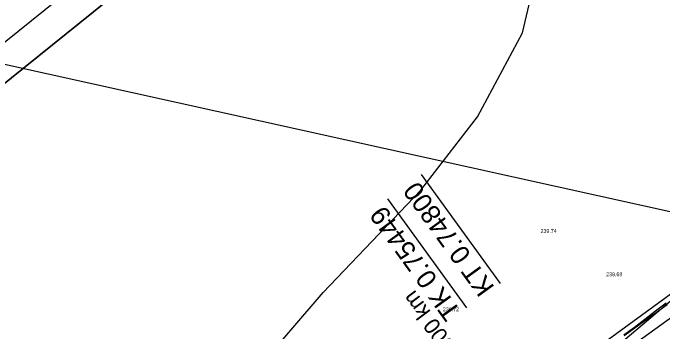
# Model space of a CAD drawing. Extents: x -555887 to -552101, y -1100251 to -1096546.
# Drawn here: x -555426.4 to -555324.6, y -1098653.3 to -1098603.5 of the extents above; entities that cross this region are included whole.
import ezdxf

# ---------------------------------------------------------------- set-up
doc = ezdxf.new("R2010")
doc.units = 0
for name, color, linetype in [('07_ELEKTRO', 7, 'Continuous'), ('PARCELY_cesty', 7, 'Continuous'), ('POLYGONY_SITUACE_PF_POPISY', 7, 'Continuous'), ('POLYGONY_SITUACE_PO', 7, 'Continuous'), ('ram_VC3-R', 7, 'Continuous'), ('vrstevnice', 7, 'Continuous'), ('Výškopis', 7, 'Continuous'), ('ZSST', 7, 'Continuous')]:
    doc.layers.add(name, color=color, linetype=linetype)

msp = doc.modelspace()

# ---------------------------------------------------------------- linework, layer by layer
for p, q in [((-555350.09, -1098645.86), (-555362.44, -1098628.75)), ((-555355.35, -1098649.65), (-555367.7, -1098632.55))]:
    msp.add_line(p, q)
at = {"layer": '07_ELEKTRO'}
msp.add_lwpolyline([(-555159.59, -1098672.59), (-555301.63, -1098639.48), (-555454.18, -1098605.67), (-555599.28, -1098573.72), (-555745.3, -1098541.15), (-555886.81, -1098509.49)], dxfattribs=at)
at = {"layer": 'PARCELY_cesty'}
msp.add_lwpolyline([(-555432.8, -1098748.4), (-555400.01, -1098712.21), (-555389.92, -1098701.56), (-555373.94, -1098686.47), (-555357.13, -1098672.28), (-555340.17, -1098659.66), (-555299.83, -1098630.2), (-555259.85, -1098600.29), (-555132.6, -1098503.99), (-555074.98, -1098461.38), (-555070.8, -1098455.67), (-555054.38, -1098443.8), (-555047.89, -1098441.68), (-555024.77, -1098425.17), (-554988.25, -1098399.71), (-554740.35, -1098228.23), (-554737.92, -1098224.21)], dxfattribs=at)
at = {"layer": 'POLYGONY_SITUACE_PO'}
for p, q in [((-555318.18, -1098647.4), (-555338.39, -1098662.07)), ((-555324.14, -1098648.93), (-555325.83, -1098650.15)), ((-555323.98, -1098649.16), (-555325.66, -1098650.38)), ((-555323.98, -1098649.16), (-555325.66, -1098650.38)), ((-555325.83, -1098650.15), (-555327.46, -1098651.46)), ((-555325.66, -1098650.38), (-555327.35, -1098651.61)), ((-555325.66, -1098650.38), (-555327.35, -1098651.61)), ((-555327.46, -1098651.46), (-555329.11, -1098652.73)), ((-555327.35, -1098651.61), (-555329.03, -1098652.83)), ((-555327.35, -1098651.61), (-555329.03, -1098652.83)), ((-555329.11, -1098652.73), (-555330.79, -1098653.96)), ((-555329.03, -1098652.83), (-555330.72, -1098654.05)), ((-555329.03, -1098652.83), (-555330.72, -1098654.05))]:
    msp.add_line(p, q, dxfattribs=at)
at = {"layer": 'ram_VC3-R'}
for points in [[(-554580.57, -1098306.86), (-554766.92, -1098075.6), (-555584.52, -1098734.41), (-555398.17, -1098965.67), (-554580.57, -1098306.86)], [(-555397.41, -1098958.64), (-555577.49, -1098735.16), (-554767.68, -1098082.63), (-554587.6, -1098306.1), (-555397.41, -1098958.64)]]:
    msp.add_lwpolyline(points, dxfattribs=at)
for points in [[(-554580.57, -1098306.86), (-554766.92, -1098075.6), (-555584.52, -1098734.41), (-555398.17, -1098965.67)], [(-554587.6, -1098306.1), (-554767.68, -1098082.63), (-555577.49, -1098735.16), (-555397.41, -1098958.64)]]:
    msp.add_lwpolyline(points, close=True, dxfattribs=at)
at = {"layer": 'vrstevnice'}
msp.add_lwpolyline([(-555306.35, -1098681.23), (-555357.18, -1098717.88), (-555367.86, -1098724.9), (-555380.49, -1098729.11), (-555384.14, -1098729.53), (-555393.13, -1098727.71), (-555396.5, -1098726.02), (-555402.12, -1098719.98), (-555404.5, -1098714.93), (-555405.91, -1098704.82), (-555405.49, -1098694.85), (-555402.12, -1098681.51), (-555398.05, -1098672.52), (-555392.99, -1098664.94), (-555377.83, -1098647.25), (-555362.52, -1098631.24), (-555353.67, -1098619.73), (-555346.65, -1098606.59), (-555345.39, -1098601.19)], dxfattribs=at)
at = {"layer": 'ZSST'}
for points in [[(-555047.93, -1098442.03), (-555072.12, -1098458.86), (-555088.34, -1098470.57), (-555126.84, -1098498.87), (-555144.37, -1098512.2), (-555194.54, -1098551.36), (-555231.55, -1098580.01), (-555250.25, -1098594.37), (-555270.85, -1098609.63), (-555289.58, -1098622.71), (-555305.43, -1098634.04), (-555318.12, -1098644.14), (-555342.33, -1098664.59), (-555361.73, -1098681.61), (-555377.43, -1098695.41), (-555388.84, -1098705.7), (-555402.21, -1098718.08), (-555414.99, -1098731.34), (-555426.44, -1098743.28)], [(-555283.1, -1098643.91), (-555301.63, -1098639.48), (-555454.18, -1098605.67), (-555599.28, -1098573.72), (-555745.3, -1098541.15), (-555792.66, -1098530.65)]]:
    msp.add_lwpolyline(points, dxfattribs=at)

# ---------------------------------------------------------------- texts
for s, p in [('KT 0.74800', (-555350.91, -1098646.44)), ('TK 0.75449', (-555356.16, -1098650.24))]:
    msp.add_text(s, height=3, rotation=125.8186).set_placement(p)
at = {"layer": 'POLYGONY_SITUACE_PF_POPISY'}
msp.add_text('0.76000 km', height=2.5, rotation=126.7208, dxfattribs=at).set_placement((-555353.12, -1098660.71))
at = {"layer": 'Výškopis'}
for s, p in [('239.74', (-555343.81, -1098637.92)), ('239.68', (-555333.54, -1098644.7)), ('239.72', (-555359.1, -1098650.18))]:
    msp.add_text(s, height=0.6, dxfattribs=at).set_placement(p)

doc.saveas('drawing.dxf')
